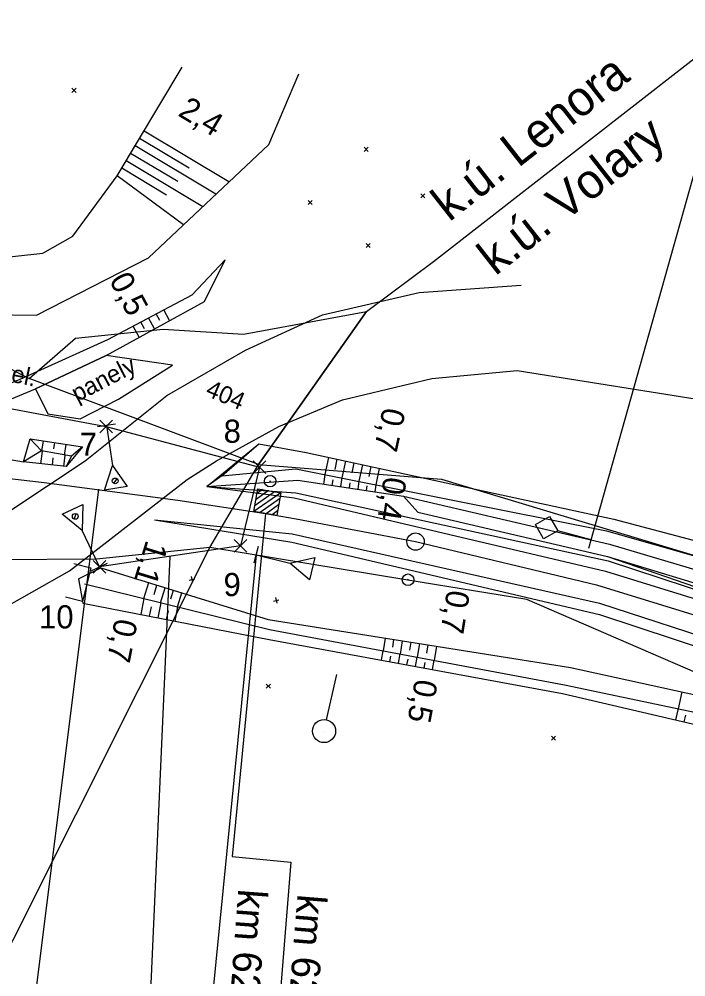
# Model space of a CAD drawing. Extents: x -804899 to -803847, y -1165742 to -1164942.
# Drawn here: x -804772 to -804714.3, y -1165158.3 to -1165075.5 of the extents above; entities that cross this region are included whole.
import ezdxf

# ---------------------------------------------------------------- set-up
doc = ezdxf.new("R2010")
doc.units = 0
for name, color, linetype in [('0381KM061-064P - Vrstva 1', 7, 'Continuous'), ('0381KM061-064P - Vrstva 16', 7, 'Continuous'), ('0381KM061-064P - Vrstva 27', 7, 'Continuous'), ('0381KM061-064P - Vrstva 3', 7, 'Continuous'), ('0381KM061-064P - Vrstva 36', 7, 'Continuous'), ('0381KM061-064P - Vrstva 4', 7, 'Continuous'), ('0381KM061-064P - Vrstva 43', 7, 'Continuous'), ('0381KM061-064P - Vrstva 48', 7, 'Continuous'), ('0381KM061-064P - Vrstva 49', 7, 'Continuous'), ('0381KM061-064P - Vrstva 51', 7, 'Continuous'), ('0381KM061-064P - Vrstva 55', 7, 'Continuous'), ('0381KM061-064P - Vrstva 57', 7, 'Continuous'), ('0381KM061-064P - Vrstva 7', 7, 'Continuous'), ('0381KM061-064P - Vrstva 8', 7, 'Continuous'), ('Default', 7, 'Continuous'), ('hran DP - hran DP', 7, 'Continuous'), ('PSR_C2_3_Lomove_body_Lenora - Vrstva 60', 7, 'Continuous'), ('PSR_C2_3_trasa_Lenora - Kabelová trasa', 7, 'Continuous'), ('SOPS', 7, 'Continuous')]:
    doc.layers.add(name, color=color, linetype=linetype)

msp = doc.modelspace()

# ---------------------------------------------------------------- linework, layer by layer
at = {"layer": '0381KM061-064P - Vrstva 1'}
for points in [[(-804783.453, -1165113.99), (-804769.784, -1165115.585), (-804758.243, -1165117.11), (-804750.67, -1165118.27), (-804748.021, -1165118.722)], [(-804748.021, -1165118.722), (-804737.69, -1165120.695), (-804722.056, -1165124.431), (-804702.108, -1165130.565), (-804682.19, -1165138.236), (-804666.439, -1165145.5)]]:
    msp.add_lwpolyline(points, dxfattribs=at)
at = {"layer": '0381KM061-064P - Vrstva 16'}
msp.add_lwpolyline([(-804770.535, -1165107.501), (-804769.468, -1165109.647), (-804766.68, -1165110.089), (-804763.361, -1165108.378), (-804758.689, -1165105.46), (-804764.444, -1165104.598), (-804770.535, -1165107.501)], dxfattribs=at)
at = {"layer": '0381KM061-064P - Vrstva 27'}
msp.add_line((-804750.306, -1165115.467), (-804750.206, -1165115.467), dxfattribs=at)
msp.add_circle((-804750.256, -1165115.467), 0.5, dxfattribs=at)
at = {"layer": '0381KM061-064P - Vrstva 3'}
for p, q in [((-804750.916, -1165116.199), (-804751.388, -1165116.533)), ((-804749.348, -1165116.467), (-804751.656, -1165118.102)), ((-804749.87, -1165116.378), (-804751.567, -1165117.579)), ((-804750.394, -1165116.288), (-804751.477, -1165117.056)), ((-804749.437, -1165116.989), (-804751.133, -1165118.191)), ((-804749.526, -1165117.513), (-804750.61, -1165118.28)), ((-804749.615, -1165118.035), (-804750.087, -1165118.369))]:
    msp.add_line(p, q, dxfattribs=at)
msp.add_lwpolyline([(-804749.684, -1165118.438), (-804751.656, -1165118.102), (-804751.319, -1165116.13), (-804749.348, -1165116.467)], close=True, dxfattribs=at)
msp.add_lwpolyline([(-804750.67, -1165118.27), (-804753.547, -1165147.904), (-804748.478, -1165148.388), (-804749.734, -1165164.119)], dxfattribs=at)
at = {"layer": '0381KM061-064P - Vrstva 36'}
for p, q in [((-804745.38, -1165136.083), (-804744.493, -1165132.183)), ((-804745.602, -1165137.058), (-804745.602, -1165137.058))]:
    msp.add_line(p, q, dxfattribs=at)
msp.add_circle((-804745.602, -1165137.058), 1, dxfattribs=at)
at = {"layer": '0381KM061-064P - Vrstva 4'}
for p, q in [((-804763.642, -1165110.553), (-804765.182, -1165110.783)), ((-804763.508, -1165115.254), (-804763.801, -1165115.646)), ((-804765.098, -1165116.15), (-804771.936, -1165170.886)), ((-804769.784, -1165115.585), (-804758.243, -1165117.11)), ((-804767.194, -1165118.739), (-804767.025, -1165118.28)), ((-804765.729, -1165123.208), (-804764.319, -1165122.55))]:
    msp.add_line(p, q, dxfattribs=at)
for points in [[(-804843.833, -1165105.728), (-804840.797, -1165106.06), (-804819.65, -1165108.38), (-804802.702, -1165110.303), (-804779.709, -1165112.392), (-804771.588, -1165113.785)], [(-804764.412, -1165110.668), (-804763.89, -1165114.106), (-804762.613, -1165115.941), (-804764.587, -1165116.247), (-804763.89, -1165114.106)], [(-804755.733, -1165115.927), (-804748.168, -1165116.905), (-804721.253, -1165123.253), (-804698.663, -1165130.219), (-804681.332, -1165136.993), (-804671.473, -1165141.648), (-804648.845, -1165153.359), (-804638.113, -1165160.035), (-804624.479, -1165168.696), (-804602.557, -1165183.067), (-804574.466, -1165201.721), (-804542.719, -1165222.837), (-804507.36, -1165246.549), (-804477.085, -1165266.816), (-804448.754, -1165285.875), (-804421.182, -1165304.145), (-804392.893, -1165323.086), (-804369.849, -1165338.366), (-804348.858, -1165352.041), (-804325.134, -1165367.981), (-804299.324, -1165385.271), (-804266.052, -1165407.314), (-804234.277, -1165428.598)], [(-804755.733, -1165115.927), (-804748.032, -1165116.485), (-804721.047, -1165122.361), (-804698.438, -1165129.771), (-804680.982, -1165136.504), (-804671.213, -1165140.894), (-804648.415, -1165152.455), (-804637.551, -1165159.434), (-804624.035, -1165168.294), (-804602.248, -1165182.377), (-804573.745, -1165201.202), (-804542.465, -1165222.561), (-804507.059, -1165246.026), (-804476.473, -1165266.236), (-804448.309, -1165285.076), (-804421.024, -1165303.102), (-804392.59, -1165322.59), (-804369.414, -1165337.648), (-804348.678, -1165351.592), (-804324.758, -1165367.42), (-804298.904, -1165384.417), (-804265.65, -1165406.497), (-804234.045, -1165428.038)], [(-804765.024, -1165122.879), (-804766.502, -1165119.732), (-804768.248, -1165118.335), (-804766.441, -1165117.481), (-804766.502, -1165119.732)], [(-804760.257, -1165118.798), (-804748.359, -1165120.009), (-804721.794, -1165126.004), (-804699.133, -1165133.383), (-804682.383, -1165139.582), (-804672.624, -1165144.091), (-804650.427, -1165155.704), (-804639.382, -1165162.287), (-804626.131, -1165170.888), (-804604.367, -1165185.52), (-804576.364, -1165204.152)], [(-804760.257, -1165118.798), (-804748.388, -1165120.746), (-804721.772, -1165126.976), (-804699.376, -1165134.382), (-804682.716, -1165140.57), (-804673.684, -1165144.668), (-804650.962, -1165156.638), (-804639.654, -1165163.015), (-804626.635, -1165171.43)]]:
    msp.add_lwpolyline(points, dxfattribs=at)
for centre in [(-804763.655, -1165115.449), (-804767.109, -1165118.51)]:
    msp.add_circle(centre, 0.248, dxfattribs=at)
at = {"layer": '0381KM061-064P - Vrstva 43'}
msp.add_lwpolyline([(-804767.225, -1165122.587), (-804765.769, -1165122.947), (-804766.487, -1165125.859), (-804767.944, -1165125.5)], dxfattribs=at)
at = {"layer": '0381KM061-064P - Vrstva 48'}
for p, q in [((-804753.817, -1165089.617), (-804761.161, -1165085.217)), ((-804757.249, -1165088.435), (-804761.547, -1165085.86)), ((-804758.238, -1165089.591), (-804762.318, -1165087.147)), ((-804754.951, -1165090.686), (-804761.932, -1165086.504)), ((-804756.086, -1165091.755), (-804762.703, -1165087.79)), ((-804759.227, -1165090.747), (-804763.089, -1165088.434)), ((-804757.736, -1165093.31), (-804763.474, -1165089.077)), ((-804759.81, -1165101.582), (-804760.11, -1165101.016)), ((-804758.952, -1165101.6), (-804759.448, -1165100.665)), ((-804761.584, -1165103.037), (-804762.097, -1165102.071)), ((-804761.129, -1165102.294), (-804761.434, -1165101.719)), ((-804760.267, -1165102.318), (-804760.772, -1165101.368)), ((-804770.005, -1165112.865), (-804769.867, -1165111.982)), ((-804769.976, -1165112.871), (-804770.102, -1165113.958)), ((-804768.964, -1165112.678), (-804768.88, -1165112.136)), ((-804768.036, -1165113.213), (-804767.892, -1165112.289)), ((-804769.037, -1165113.456), (-804769.109, -1165114.073)), ((-804768.002, -1165113.219), (-804768.115, -1165114.189)), ((-804745.51, -1165114.894), (-804745.19, -1165113.417)), ((-804744.647, -1165114.455), (-804744.457, -1165113.575)), ((-804744.039, -1165115.188), (-804743.724, -1165113.734)), ((-804743.178, -1165114.758), (-804742.991, -1165113.892)), ((-804742.568, -1165115.482), (-804742.258, -1165114.051)), ((-804741.709, -1165115.061), (-804741.525, -1165114.209)), ((-804741.097, -1165115.775), (-804740.793, -1165114.368)), ((-804745.531, -1165114.89), (-804745.654, -1165115.72)), ((-804744.841, -1165115.354), (-804744.913, -1165115.83)), ((-804744.058, -1165115.184), (-804744.171, -1165115.941)), ((-804743.364, -1165115.619), (-804743.429, -1165116.052)), ((-804742.585, -1165115.478), (-804742.687, -1165116.163)), ((-804741.887, -1165115.885), (-804741.946, -1165116.274)), ((-804741.112, -1165115.772), (-804741.204, -1165116.385)), ((-804761.183, -1165125.614), (-804760.758, -1165124.234)), ((-804760.293, -1165125.257), (-804760.045, -1165124.454)), ((-804759.732, -1165125.971), (-804759.332, -1165124.674)), ((-804758.852, -1165125.648), (-804758.619, -1165124.894)), ((-804758.281, -1165126.329), (-804757.906, -1165125.115)), ((-804761.174, -1165125.616), (-804761.442, -1165126.991)), ((-804759.718, -1165125.975), (-804759.972, -1165127.277)), ((-804760.55, -1165126.331), (-804760.707, -1165127.134)), ((-804759.089, -1165126.661), (-804759.237, -1165127.42)), ((-804758.263, -1165126.334), (-804758.502, -1165127.563)), ((-804740.47, -1165130.132), (-804740.295, -1165129.026)), ((-804739.661, -1165129.819), (-804739.554, -1165129.143)), ((-804738.995, -1165130.408), (-804738.813, -1165129.261)), ((-804738.183, -1165130.078), (-804738.072, -1165129.378)), ((-804740.52, -1165130.123), (-804740.67, -1165130.935)), ((-804737.52, -1165130.683), (-804737.332, -1165129.495)), ((-804736.706, -1165130.337), (-804736.591, -1165129.612)), ((-804736.045, -1165130.958), (-804735.85, -1165129.73)), ((-804739.843, -1165130.585), (-804739.933, -1165131.071)), ((-804739.046, -1165130.398), (-804739.195, -1165131.207)), ((-804738.369, -1165130.859), (-804738.458, -1165131.343)), ((-804737.572, -1165130.673), (-804737.72, -1165131.479)), ((-804736.894, -1165131.133), (-804736.983, -1165131.615)), ((-804736.097, -1165130.949), (-804736.245, -1165131.751)), ((-804714.945, -1165135.134), (-804714.625, -1165133.678)), ((-804714.989, -1165135.125), (-804715.214, -1165136.095)), ((-804714.347, -1165135.674), (-804714.484, -1165136.265))]:
    msp.add_line(p, q, dxfattribs=at)
at = {"layer": '0381KM061-064P - Vrstva 49'}
for p, q in [((-804767.043, -1165081.875), (-804767.397, -1165081.521)), ((-804767.043, -1165081.521), (-804767.397, -1165081.875)), ((-804741.772, -1165086.971), (-804742.126, -1165086.617)), ((-804741.772, -1165086.617), (-804742.126, -1165086.971)), ((-804746.616, -1165091.562), (-804746.97, -1165091.208)), ((-804746.616, -1165091.208), (-804746.97, -1165091.562)), ((-804736.878, -1165090.989), (-804737.232, -1165090.635)), ((-804736.878, -1165090.635), (-804737.232, -1165090.989)), ((-804741.6, -1165095.286), (-804741.954, -1165094.932)), ((-804741.6, -1165094.932), (-804741.954, -1165095.286)), ((-804770.535, -1165107.501), (-804764.444, -1165104.598)), ((-804767.436, -1165113.319), (-804770.041, -1165112.859)), ((-804757.268, -1165124.011), (-804756.782, -1165123.897)), ((-804757.082, -1165123.711), (-804756.968, -1165124.197)), ((-804749.983, -1165125.828), (-804749.497, -1165125.714)), ((-804749.797, -1165125.528), (-804749.683, -1165126.014)), ((-804750.241, -1165133.351), (-804750.595, -1165132.997)), ((-804750.241, -1165132.997), (-804750.595, -1165133.351)), ((-804725.58, -1165137.854), (-804725.934, -1165137.5)), ((-804725.58, -1165137.5), (-804725.934, -1165137.854))]:
    msp.add_line(p, q, dxfattribs=at)
for points in [[(-804769.918, -1165095.766), (-804767.328, -1165094.301), (-804763.474, -1165089.077), (-804757.859, -1165079.705)], [(-804782.933, -1165100.952), (-804770.452, -1165101.128), (-804760.766, -1165096.165), (-804750.377, -1165086.376), (-804747.774, -1165080.287)], [(-804834.138, -1165089.824), (-804812.848, -1165092.564), (-804796.393, -1165094.52), (-804782.729, -1165096.032), (-804774.669, -1165096.277), (-804769.918, -1165095.766)], [(-804778.125, -1165109.25), (-804771.874, -1165106.665), (-804764.298, -1165103.24), (-804757.01, -1165099.37), (-804754.139, -1165096.348)], [(-804764.444, -1165104.598), (-804755.942, -1165099.957), (-804754.139, -1165096.348)], [(-804778.59, -1165110.844), (-804770.535, -1165107.501)], [(-804771.021, -1165111.803), (-804770.041, -1165112.859), (-804771.588, -1165113.785)], [(-804766.482, -1165112.508), (-804767.436, -1165113.319), (-804767.889, -1165114.215)], [(-804755.733, -1165115.927), (-804751.237, -1165112.247), (-804747.153, -1165112.992), (-804720.555, -1165118.745), (-804697.457, -1165124.856)], [(-804754.423, -1165115.02), (-804751.237, -1165112.247)], [(-804754.423, -1165115.02), (-804748.035, -1165114.39), (-804721.192, -1165119.749), (-804697.281, -1165126.544)], [(-804754.423, -1165115.02), (-804755.733, -1165115.927)], [(-804755.733, -1165115.927), (-804747.853, -1165115.391), (-804738.732, -1165116.754), (-804720.925, -1165120.918), (-804697.629, -1165127.819)], [(-804738.732, -1165116.754), (-804737.496, -1165118.134), (-804721.084, -1165121.979), (-804698.174, -1165128.955), (-804680.733, -1165135.834), (-804670.748, -1165140.269), (-804648.415, -1165152.455)], [(-804721.084, -1165121.979), (-804698.438, -1165129.771), (-804680.982, -1165136.504), (-804671.213, -1165140.894), (-804648.415, -1165152.455)], [(-804766.835, -1165123.914), (-804764.887, -1165122.959), (-804750.44, -1165127.42), (-804724.293, -1165131.559), (-804700.35, -1165136.808), (-804683.355, -1165141.958), (-804673.479, -1165145.601), (-804651.73, -1165158.215)], [(-804766.835, -1165123.914), (-804766.462, -1165126.013)], [(-804766.318, -1165124.347), (-804750.308, -1165128.296), (-804724.802, -1165133.057), (-804699.443, -1165138.401), (-804683.582, -1165142.5), (-804673.524, -1165146.323), (-804651.73, -1165158.215)], [(-804766.462, -1165126.013), (-804750.339, -1165129.153), (-804724.988, -1165133.826)], [(-804724.988, -1165133.826), (-804700.388, -1165139.537), (-804683.823, -1165143.076), (-804673.785, -1165147.18), (-804651.73, -1165158.215)]]:
    msp.add_lwpolyline(points, dxfattribs=at)
msp.add_lwpolyline([(-804771.588, -1165113.785), (-804771.021, -1165111.803), (-804766.482, -1165112.508), (-804767.889, -1165114.215)], close=True, dxfattribs=at)
at = {"layer": '0381KM061-064P - Vrstva 51'}
for points in [[(-804799.401, -1165124.127), (-804788.787, -1165123.564), (-804781.178, -1165122.085), (-804777.377, -1165120.679), (-804772.772, -1165118.025), (-804766.254, -1165113.723), (-804759.193, -1165108.078), (-804752.39, -1165104.15), (-804745.737, -1165101.091), (-804737.367, -1165099.155), (-804728.561, -1165098.534)], [(-804786.505, -1165130.38), (-804780.047, -1165129.084), (-804774.134, -1165126.908), (-804767.616, -1165123.226), (-804757.446, -1165115.319), (-804754.899, -1165113.701), (-804749.494, -1165110.738), (-804743.99, -1165108.455), (-804736.292, -1165106.603), (-804728.9, -1165105.899)], [(-804728.9, -1165105.899), (-804711.537, -1165108.671), (-804704.349, -1165111.804), (-804683.685, -1165124.094), (-804676.948, -1165128.427), (-804667.361, -1165134.407), (-804645.714, -1165148.297), (-804634.703, -1165155.23), (-804621.633, -1165163.621), (-804599.185, -1165178.232), (-804569.67, -1165197.161), (-804538.422, -1165216.767), (-804503.409, -1165238.938), (-804472.822, -1165258.548), (-804444.565, -1165276.404), (-804415.818, -1165294.725), (-804384.702, -1165314.566), (-804342.586, -1165341.716), (-804321.799, -1165355.02), (-804291.771, -1165374.224), (-804262.453, -1165392.961)]]:
    msp.add_lwpolyline(points, dxfattribs=at)
at = {"layer": '0381KM061-064P - Vrstva 55'}
msp.add_lwpolyline([(-804834.02, -1165173.21), (-804777.95, -1165165.95), (-804761.65, -1165133.49), (-804755.48, -1165121.19), (-804751.26, -1165114.04), (-804741.92, -1165100.8), (-804736.13, -1165096.49), (-804701.79, -1165069.72), (-804628.296, -1165012.443)], dxfattribs=at)
msp.add_lwpolyline([(-804771.09, -1165106.6), (-804767.08, -1165103.1), (-804759.5, -1165102.35), (-804752.56, -1165102.78), (-804741.92, -1165100.8), (-804751.26, -1165114.04)], close=True, dxfattribs=at)
at = {"layer": '0381KM061-064P - Vrstva 7'}
msp.add_line((-804738.289, -1165124.002), (-804738.387, -1165123.978), dxfattribs=at)
for centre, radius in [((-804737.69, -1165120.695), 0.75), ((-804738.338, -1165123.99), 0.5)]:
    msp.add_circle(centre, radius, dxfattribs=at)
at = {"layer": '0381KM061-064P - Vrstva 8'}
for p, q in [((-804722.504, -1165120.543), (-804702.468, -1165049.266)), ((-804722.702, -1165121.266), (-804722.306, -1165119.82)), ((-804751.3, -1165121.108), (-804751.658, -1165122.566)), ((-804751.479, -1165121.837), (-804755.655, -1165164.119)), ((-804746.86, -1165123.997), (-804748.565, -1165122.549))]:
    msp.add_line(p, q, dxfattribs=at)
for points in [[(-804722.504, -1165120.543), (-804725.397, -1165119.752), (-804726.626, -1165120.453), (-804727.327, -1165119.224), (-804726.098, -1165118.524), (-804725.397, -1165119.752)], [(-804751.479, -1165121.837), (-804748.565, -1165122.549), (-804746.385, -1165122.054), (-804746.86, -1165123.997), (-804748.565, -1165122.549)]]:
    msp.add_lwpolyline(points, dxfattribs=at)
at = {"layer": 'hran DP - hran DP'}
for p, q in [((-804752.56, -1165102.78), (-804741.92, -1165100.8)), ((-804741.92, -1165100.8), (-804751.26, -1165114.04)), ((-804767.08, -1165103.1), (-804759.5, -1165102.35)), ((-804759.5, -1165102.35), (-804752.56, -1165102.78)), ((-804777.08, -1165103.56), (-804771.09, -1165106.6)), ((-804771.09, -1165106.6), (-804767.08, -1165103.1)), ((-804751.26, -1165114.04), (-804735.44, -1165115.31)), ((-804735.44, -1165115.31), (-804706.98, -1165123.89)), ((-804755.48, -1165121.19), (-804765.27, -1165122.22)), ((-804738.35, -1165124.03), (-804755.48, -1165121.19)), ((-804765.27, -1165122.22), (-804781.51, -1165122.32)), ((-804728.07, -1165125.68), (-804738.35, -1165124.03)), ((-804647.39, -1165160.7), (-804728.07, -1165125.68))]:
    msp.add_line(p, q, dxfattribs=at)
at = {"layer": 'PSR_C2_3_Lomove_body_Lenora - Vrstva 60'}
for p, q in [((-804764.994, -1165111.291), (-804763.894, -1165110.191)), ((-804763.894, -1165111.291), (-804764.994, -1165110.191)), ((-804751.732, -1165114.818), (-804750.632, -1165113.718)), ((-804750.632, -1165114.818), (-804751.732, -1165113.718)), ((-804753.376, -1165121.618), (-804752.276, -1165120.518)), ((-804752.276, -1165121.618), (-804753.376, -1165120.518)), ((-804765.574, -1165123.429), (-804764.474, -1165122.329)), ((-804764.474, -1165123.429), (-804765.574, -1165122.329))]:
    msp.add_line(p, q, dxfattribs=at)
at = {"layer": 'PSR_C2_3_trasa_Lenora - Kabelová trasa'}
msp.add_lwpolyline([(-804776.847, -1165103.594), (-804778.343, -1165103.409), (-804778.917, -1165108.044), (-804764.444, -1165110.741), (-804751.182, -1165114.268), (-804752.826, -1165121.068), (-804765.024, -1165122.879)], dxfattribs=at)
at = {"layer": 'SOPS'}
msp.add_lwpolyline([(-804758.925, -1165121.974), (-804762.017, -1165191.306), (-804752.78, -1165196.937)], dxfattribs=at)

# ---------------------------------------------------------------- texts
at = {"layer": '0381KM061-064P - Vrstva 16'}
for s, rotation, p in [('panel.', 348.07068, (-804775.996, -1165106.177)), ('panely', 27.27186, (-804766.953, -1165108.661))]:
    msp.add_text(s, height=1.5, rotation=rotation, dxfattribs=at).set_placement(p)
at = {"layer": '0381KM061-064P - Vrstva 3'}
msp.add_text('km 62,786', height=2.5, rotation=265.31685, dxfattribs=at).set_placement((-804747.885, -1165151.101))
at = {"layer": '0381KM061-064P - Vrstva 48'}
for s, rotation, p in [('2,4', 329.07312, (-804758.312, -1165083.848)), ('0,5', 297.96874, (-804764.215, -1165098.091)), ('0,7', 257.79525, (-804740.497, -1165109.01)), ('0,4', 261.50088, (-804740.429, -1165115.012)), ('1,1', 252.84016, (-804760.962, -1165120.493)), ('0,7', 261.00487, (-804734.96, -1165124.788)), ('0,7', 258.97943, (-804763.666, -1165127.248)), ('0,5', 259.55579, (-804737.72, -1165132.48))]:
    msp.add_text(s, height=2, rotation=rotation, dxfattribs=at).set_placement(p)
at = {"layer": '0381KM061-064P - Vrstva 55'}
for s, p in [('k.ú. Lenora', (-804734.781, -1165093.121)), ('k.ú. Volary', (-804730.797, -1165097.785))]:
    msp.add_text(s, height=3, rotation=38.10401, dxfattribs=at).set_placement(p)
at = {"layer": '0381KM061-064P - Vrstva 57'}
msp.add_text('404', height=1.5, rotation=336.9346, dxfattribs=at).set_placement((-804755.929, -1165108.038))
at = {"layer": '0381KM061-064P - Vrstva 8'}
msp.add_text('km 62,786', height=2.5, rotation=265.78076, dxfattribs=at).set_placement((-804753.012, -1165150.656))
at = {"layer": 'Default'}
for s, p in [('8', (-804754.276, -1165112.153)), ('7', (-804766.714, -1165113.279)), ('9', (-804754.288, -1165125.402)), ('10', (-804770.232, -1165128.193))]:
    msp.add_text(s, height=2, dxfattribs=at).set_placement(p)

doc.saveas('drawing.dxf')
